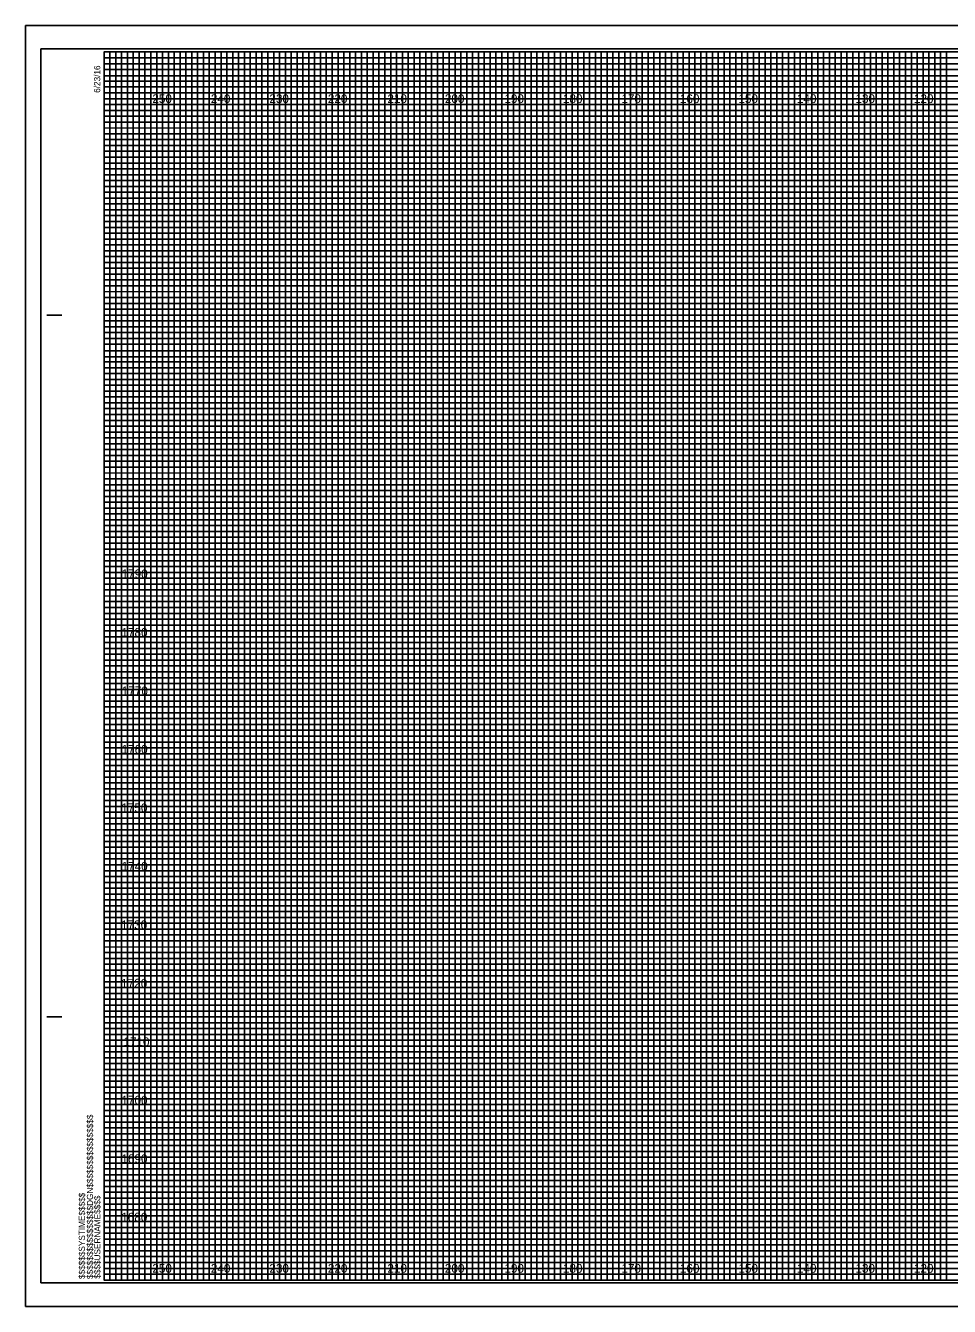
# Model space of a CAD drawing. Extents: x -13 to 1780, y -15 to 3284.
# Drawn here: x 1098.4 to 1256.3, y 208.7 to 427.7 of the extents above; entities that cross this region are included whole.
import ezdxf

# ---------------------------------------------------------------- set-up
doc = ezdxf.new("R2010")
doc.units = 0
for name, color, linetype in [('Prop Retaining Wall', 7, 'Continuous'), ('Prop SS Cut Line', 7, 'Continuous'), ('Prop SS Fill Line', 7, 'Continuous'), ('Prop SS Transition Line', 7, 'Continuous'), ('Prop XS Earthwork Shape', 7, 'Continuous'), ('Prop XS Noise Wall', 7, 'Continuous'), ('Prop XS Station Labels', 7, 'Continuous'), ('Raster_Level_0', 7, 'Continuous'), ('Scratch_Level_3', 7, 'Continuous'), ('Scratch_Level_7', 7, 'Continuous'), ('Typical Bridge Rail CELL', 7, 'Continuous')]:
    doc.layers.add(name, color=color, linetype=linetype)

msp = doc.modelspace()

# ---------------------------------------------------------------- linework, layer by layer
at = {"layer": 'Prop Retaining Wall'}
for p, q in [((1101.99, 378.2), (1104.49, 378.2)), ((1102.09, 378.2), (1104.59, 378.2)), ((1101.99, 258.2), (1104.49, 258.2)), ((1102.09, 258.2), (1104.59, 258.2)), ((1111.79, 213.2), (1111.79, 213.2)), ((1111.79, 213.2), (1111.79, 213.2)), ((1111.79, 213.2), (1111.79, 213.2)), ((1111.79, 213.2), (1111.79, 213.2)), ((1111.79, 213.2), (1111.79, 213.2)), ((1111.79, 213.2), (1111.79, 213.2)), ((1111.79, 213.2), (1111.79, 213.2))]:
    msp.add_line(p, q, dxfattribs=at)
msp.add_lwpolyline([(1431.79, 423.2), (1111.79, 423.2), (1111.79, 213.2), (1431.79, 213.2)], close=True, dxfattribs=at)
at = {"layer": 'Prop SS Cut Line'}
for points in [[(1111.79, 423.2), (1116.79, 423.2), (1116.79, 213.2), (1126.79, 213.2), (1126.79, 423.2), (1136.79, 423.2), (1136.79, 213.2), (1146.79, 213.2), (1146.79, 423.2), (1156.79, 423.2), (1156.79, 213.2), (1166.79, 213.2), (1166.79, 423.2), (1176.79, 423.2), (1176.79, 213.2), (1186.79, 213.2), (1186.79, 423.2), (1196.79, 423.2), (1196.79, 213.2), (1206.79, 213.2), (1206.79, 423.2), (1216.79, 423.2), (1216.79, 213.2), (1226.79, 213.2), (1226.79, 423.2), (1236.79, 423.2), (1236.79, 213.2), (1246.79, 213.2), (1246.79, 423.2), (1256.79, 423.2)], [(1111.79, 418.2), (1386.79, 418.2)], [(1111.79, 398.2), (1431.79, 398.2), (1431.79, 408.2), (1111.79, 408.2)], [(1111.79, 378.2), (1431.79, 378.2), (1431.79, 388.2), (1111.79, 388.2)], [(1111.79, 358.2), (1431.79, 358.2), (1431.79, 368.2), (1111.79, 368.2)], [(1111.79, 338.2), (1431.79, 338.2), (1431.79, 348.2), (1111.79, 348.2)], [(1111.79, 318.2), (1431.79, 318.2), (1431.79, 328.2), (1111.79, 328.2)], [(1111.79, 298.2), (1431.79, 298.2), (1431.79, 308.2), (1111.79, 308.2)], [(1111.79, 278.2), (1431.79, 278.2), (1431.79, 288.2), (1111.79, 288.2)], [(1111.79, 258.2), (1431.79, 258.2), (1431.79, 268.2), (1111.79, 268.2)], [(1111.79, 238.2), (1431.79, 238.2), (1431.79, 248.2), (1111.79, 248.2)], [(1111.79, 218.2), (1431.79, 218.2), (1431.79, 228.2), (1111.79, 228.2)]]:
    msp.add_lwpolyline(points, dxfattribs=at)
at = {"layer": 'Prop SS Fill Line'}
for p, q in [((1121.79, 423.2), (1111.79, 423.2)), ((1121.79, 213.2), (1121.79, 423.2)), ((1141.79, 423.2), (1131.79, 423.2)), ((1131.79, 423.2), (1131.79, 213.2)), ((1141.79, 213.2), (1141.79, 423.2)), ((1161.79, 423.2), (1151.79, 423.2)), ((1151.79, 423.2), (1151.79, 213.2)), ((1161.79, 213.2), (1161.79, 423.2)), ((1181.79, 423.2), (1171.79, 423.2)), ((1171.79, 423.2), (1171.79, 213.2)), ((1181.79, 213.2), (1181.79, 423.2)), ((1201.79, 423.2), (1191.79, 423.2)), ((1191.79, 423.2), (1191.79, 213.2)), ((1201.79, 213.2), (1201.79, 423.2)), ((1221.79, 423.2), (1211.79, 423.2)), ((1211.79, 423.2), (1211.79, 213.2)), ((1221.79, 213.2), (1221.79, 423.2)), ((1241.79, 423.2), (1231.79, 423.2)), ((1231.79, 423.2), (1231.79, 213.2)), ((1241.79, 213.2), (1241.79, 423.2)), ((1261.79, 423.2), (1251.79, 423.2)), ((1251.79, 423.2), (1251.79, 213.2)), ((1131.79, 213.2), (1121.79, 213.2)), ((1151.79, 213.2), (1141.79, 213.2)), ((1171.79, 213.2), (1161.79, 213.2)), ((1191.79, 213.2), (1181.79, 213.2)), ((1211.79, 213.2), (1201.79, 213.2)), ((1231.79, 213.2), (1221.79, 213.2)), ((1251.79, 213.2), (1241.79, 213.2))]:
    msp.add_line(p, q, dxfattribs=at)
for points in [[(1111.79, 413.2), (1431.79, 413.2), (1431.79, 403.2), (1111.79, 403.2)], [(1111.79, 393.2), (1431.79, 393.2), (1431.79, 383.2), (1111.79, 383.2)], [(1111.79, 373.2), (1431.79, 373.2), (1431.79, 363.2), (1111.79, 363.2)], [(1111.79, 353.2), (1431.79, 353.2), (1431.79, 343.2), (1111.79, 343.2)], [(1111.79, 333.2), (1431.79, 333.2), (1431.79, 323.2), (1111.79, 323.2)], [(1111.79, 313.2), (1431.79, 313.2), (1431.79, 303.2), (1111.79, 303.2)], [(1111.79, 293.2), (1431.79, 293.2), (1431.79, 283.2), (1111.79, 283.2)], [(1111.79, 273.2), (1431.79, 273.2), (1431.79, 263.2), (1111.79, 263.2)], [(1111.79, 253.2), (1431.79, 253.2), (1431.79, 243.2), (1111.79, 243.2)], [(1111.79, 233.2), (1431.79, 233.2), (1431.79, 223.2), (1111.79, 223.2)]]:
    msp.add_lwpolyline(points, dxfattribs=at)
at = {"layer": 'Prop SS Transition Line'}
for p, q in [((1111.79, 422.2), (1371.79, 422.2)), ((1371.79, 421.18), (1111.79, 421.18)), ((1111.79, 421.18), (1111.79, 420.2)), ((1111.79, 420.2), (1371.79, 420.2)), ((1371.79, 419.09), (1111.79, 419.09)), ((1111.79, 419.09), (1111.79, 417.2)), ((1111.79, 417.2), (1431.79, 417.2))]:
    msp.add_line(p, q, dxfattribs=at)
for points in [[(1111.79, 416.2), (1381.79, 416.2), (1431.79, 416.2), (1431.79, 415.2), (1111.79, 415.2)], [(1111.79, 414.2), (1431.79, 414.2), (1431.79, 412.2), (1111.79, 412.2)], [(1111.79, 411.2), (1431.79, 411.2), (1431.79, 410.2), (1111.79, 410.18)], [(1111.79, 409.2), (1431.79, 409.2), (1431.79, 407.2), (1111.79, 407.2)], [(1111.79, 406.2), (1431.79, 406.2), (1431.79, 405.2), (1111.79, 405.2)], [(1111.79, 404.2), (1431.79, 404.2), (1431.79, 402.2), (1111.79, 402.2)], [(1111.79, 401.2), (1431.79, 401.2), (1431.79, 400.2), (1111.79, 400.2)], [(1111.79, 399.2), (1431.79, 399.2), (1431.79, 397.2), (1111.79, 397.2)], [(1111.79, 396.2), (1431.79, 396.2), (1431.79, 395.2), (1111.79, 395.2)], [(1111.79, 394.2), (1431.79, 394.2), (1431.79, 392.2), (1111.79, 392.2)], [(1111.79, 391.2), (1431.79, 391.2), (1431.79, 390.2), (1111.79, 390.2)], [(1111.79, 389.2), (1431.79, 389.2), (1431.79, 387.15), (1431.79, 386.2), (1431.79, 385.2), (1111.79, 385.2)], [(1111.79, 387.2), (1431.79, 387.2), (1431.79, 386.2), (1111.79, 386.2)], [(1111.79, 384.2), (1431.79, 384.2), (1431.79, 382.2), (1111.79, 382.23)], [(1111.79, 382.23), (1431.79, 382.2), (1431.79, 381.2), (1111.79, 381.2)], [(1111.79, 380.2), (1431.79, 380.2), (1431.79, 379.2), (1111.79, 379.2)], [(1111.79, 377.2), (1431.79, 377.2), (1431.79, 376.2), (1111.79, 376.2)], [(1111.79, 375.2), (1431.79, 375.2), (1431.79, 374.2), (1111.79, 374.2)], [(1111.72, 372.09), (1431.79, 372.09), (1431.79, 371.08), (1111.72, 371.08)], [(1111.79, 370.2), (1431.79, 370.2), (1431.79, 369.2), (1111.79, 369.2)], [(1111.79, 367.2), (1431.79, 367.2), (1431.79, 366.2), (1111.79, 366.2)], [(1111.79, 365.2), (1431.79, 365.2), (1431.79, 364.2), (1111.79, 364.2)], [(1111.79, 362.2), (1431.79, 362.2), (1431.79, 361.2), (1111.79, 361.2)], [(1111.79, 360.2), (1431.79, 360.2), (1431.79, 359.2), (1111.79, 359.2)], [(1111.79, 357.2), (1431.79, 357.2), (1431.79, 356.2), (1111.79, 356.2)], [(1111.79, 355.2), (1431.79, 355.2), (1431.79, 354.2), (1111.79, 354.2)], [(1111.79, 352.2), (1431.79, 352.2), (1431.78, 351.18), (1111.79, 351.2)], [(1111.79, 350.2), (1431.79, 350.2), (1431.79, 349.2), (1111.79, 349.2)], [(1111.79, 347.2), (1431.79, 347.2), (1431.79, 346.2), (1111.79, 346.2)], [(1111.79, 345.2), (1431.79, 345.2), (1431.79, 344.2), (1111.79, 344.2)], [(1111.79, 342.2), (1431.79, 342.2), (1431.79, 341.2), (1111.79, 341.2)], [(1111.79, 340.2), (1431.79, 340.2), (1431.79, 339.2), (1111.79, 339.2)], [(1111.79, 337.2), (1431.79, 337.2), (1431.79, 336.2), (1111.79, 336.2)], [(1111.79, 335.2), (1431.79, 335.2), (1431.79, 334.2), (1111.79, 334.2)], [(1111.79, 332.2), (1431.79, 332.2), (1431.79, 331.2), (1111.79, 331.2)], [(1111.79, 330.19), (1431.86, 330.11), (1431.79, 329.2), (1111.79, 329.2)], [(1111.79, 327.2), (1431.79, 327.2), (1431.79, 326.2), (1111.79, 326.2)], [(1111.79, 325.2), (1431.79, 325.2), (1431.79, 324.2), (1111.79, 324.2)], [(1111.79, 322.2), (1431.79, 322.2), (1431.79, 321.2), (1111.79, 321.2)], [(1111.79, 320.2), (1431.79, 320.2), (1431.79, 319.2), (1111.79, 319.2)], [(1111.79, 317.2), (1431.79, 317.2), (1431.79, 316.2), (1111.79, 316.2)], [(1111.79, 315.2), (1431.79, 315.2), (1431.79, 314.2), (1111.79, 314.2)], [(1111.79, 312.2), (1431.79, 312.2), (1431.79, 311.2), (1111.79, 311.2)], [(1111.79, 310.2), (1431.79, 310.2), (1431.79, 309.2), (1111.79, 309.2)], [(1111.79, 307.2), (1431.79, 307.2), (1431.79, 306.2), (1111.79, 306.2)], [(1111.79, 305.2), (1431.79, 305.2), (1431.79, 304.2), (1111.79, 304.2)], [(1111.79, 302.2), (1431.79, 302.2), (1431.79, 301.2), (1111.79, 301.2)], [(1111.79, 300.2), (1431.79, 300.2), (1431.79, 299.2), (1111.79, 299.2)], [(1111.79, 297.2), (1431.79, 297.2), (1431.79, 296.2), (1111.79, 296.2)], [(1111.79, 295.2), (1431.79, 295.2), (1431.79, 294.2), (1111.79, 294.2)], [(1111.79, 292.2), (1431.79, 292.2), (1431.78, 291.18), (1111.79, 291.2)], [(1111.79, 290.2), (1431.79, 290.2), (1431.79, 289.2), (1111.79, 289.2)], [(1111.79, 287.2), (1431.79, 287.2), (1431.79, 286.2), (1111.79, 286.2)], [(1111.79, 285.2), (1431.79, 285.2), (1431.79, 284.2), (1111.79, 284.2)], [(1111.79, 282.2), (1431.79, 282.2), (1431.79, 281.2), (1111.79, 281.2)], [(1111.79, 280.2), (1431.79, 280.2), (1431.79, 279.2), (1111.79, 279.2)], [(1111.79, 277.2), (1431.79, 277.2), (1431.79, 276.2), (1111.79, 276.2)], [(1111.79, 275.2), (1431.79, 275.2), (1431.79, 274.2), (1111.79, 274.2)], [(1111.79, 272.2), (1431.79, 272.2), (1431.79, 271.2), (1111.79, 271.2)], [(1111.79, 270.19), (1431.86, 270.11), (1431.79, 269.2), (1111.79, 269.2)], [(1111.79, 267.2), (1431.79, 267.2), (1431.79, 266.2), (1111.79, 266.2)], [(1111.79, 265.2), (1431.79, 265.2), (1431.79, 264.2), (1111.79, 264.2)], [(1111.79, 262.2), (1431.79, 262.2), (1431.79, 261.2), (1111.79, 261.2)], [(1111.79, 260.2), (1431.79, 260.2), (1431.79, 259.2), (1111.79, 259.2)], [(1111.79, 257.2), (1431.79, 257.2), (1431.79, 256.2), (1111.79, 256.2)], [(1111.79, 255.2), (1431.79, 255.2), (1431.79, 254.2), (1111.79, 254.2)], [(1111.79, 252.2), (1431.79, 252.2), (1431.79, 251.2), (1111.79, 251.2)], [(1111.79, 250.2), (1431.79, 250.2), (1431.79, 249.2), (1111.79, 249.2)], [(1111.79, 247.2), (1431.79, 247.2), (1431.79, 246.2), (1111.79, 246.2)], [(1111.79, 245.2), (1431.79, 245.2), (1431.79, 244.2), (1111.79, 244.2)], [(1111.79, 242.2), (1431.79, 242.2), (1431.79, 241.2), (1111.79, 241.2)], [(1111.79, 240.2), (1431.79, 240.2), (1431.79, 239.2), (1111.79, 239.2)], [(1111.79, 237.2), (1431.79, 237.2), (1431.79, 236.2), (1111.79, 236.2)], [(1111.79, 235.2), (1431.79, 235.2), (1431.79, 234.2), (1111.79, 234.2)], [(1111.79, 232.2), (1431.79, 232.2), (1431.79, 231.2), (1111.79, 231.2)], [(1111.79, 230.2), (1431.79, 230.2), (1431.79, 229.2), (1111.79, 229.2)], [(1111.79, 227.2), (1431.79, 227.2), (1431.79, 226.2), (1111.79, 226.2)], [(1111.79, 225.2), (1431.79, 225.2), (1431.79, 224.2), (1111.79, 224.2)], [(1111.79, 222.2), (1431.79, 222.2), (1431.79, 221.2), (1111.79, 221.2)], [(1111.79, 220.2), (1431.79, 220.2), (1431.79, 219.2), (1111.79, 219.2)], [(1111.79, 217.2), (1431.79, 217.2), (1431.79, 216.2), (1111.79, 216.2)], [(1111.79, 215.2), (1431.79, 215.2), (1431.79, 214.2), (1111.79, 214.2)]]:
    msp.add_lwpolyline(points, dxfattribs=at)
at = {"layer": 'Prop XS Earthwork Shape'}
msp.add_lwpolyline([(1098.39, 208.7), (1435.09, 208.7), (1435.09, 427.7), (1098.39, 427.7)], close=True, dxfattribs=at)
at = {"layer": 'Prop XS Noise Wall'}
for p, q in [((1121.79, 213.2), (1121.79, 423.2)), ((1131.79, 213.2), (1131.79, 423.2)), ((1141.79, 213.2), (1141.79, 423.2)), ((1151.79, 213.2), (1151.79, 423.2)), ((1161.79, 213.2), (1161.79, 423.2)), ((1171.79, 213.2), (1171.79, 423.2)), ((1181.79, 213.2), (1181.79, 423.2)), ((1191.79, 213.2), (1191.79, 423.2)), ((1201.79, 213.2), (1201.79, 423.2)), ((1211.79, 213.2), (1211.79, 423.2)), ((1221.79, 213.2), (1221.79, 423.2)), ((1231.79, 213.2), (1231.79, 423.2)), ((1241.79, 213.2), (1241.79, 423.2)), ((1251.79, 213.2), (1251.79, 423.2)), ((1111.79, 413.2), (1431.79, 413.2)), ((1111.79, 403.2), (1431.79, 403.2)), ((1111.79, 393.2), (1431.79, 393.2)), ((1111.79, 383.2), (1431.79, 383.2)), ((1111.79, 373.2), (1431.79, 373.2)), ((1111.79, 363.2), (1431.79, 363.2)), ((1111.79, 353.2), (1431.79, 353.2)), ((1111.79, 343.2), (1431.79, 343.2)), ((1111.79, 333.2), (1431.79, 333.2)), ((1111.79, 323.2), (1431.79, 323.2)), ((1111.79, 313.2), (1431.79, 313.2)), ((1111.79, 303.2), (1431.79, 303.2)), ((1111.79, 293.2), (1431.79, 293.2)), ((1111.79, 283.2), (1431.79, 283.2)), ((1111.79, 273.2), (1431.79, 273.2)), ((1111.79, 263.2), (1431.79, 263.2)), ((1111.79, 253.2), (1431.79, 253.2)), ((1111.79, 243.2), (1431.79, 243.2)), ((1111.79, 233.2), (1431.79, 233.2)), ((1111.79, 223.2), (1431.79, 223.2))]:
    msp.add_line(p, q, dxfattribs=at)
at = {"layer": 'Prop XS Station Labels'}
for p, q in [((1435.09, 427.7), (1098.39, 427.7)), ((1098.39, 427.7), (1098.39, 208.7)), ((1098.39, 208.7), (1435.09, 208.7))]:
    msp.add_line(p, q, dxfattribs=at)
at = {"layer": 'Scratch_Level_7'}
msp.add_lwpolyline([(1100.99, 212.7), (1434.19, 212.7), (1434.19, 423.7), (1100.99, 423.7)], close=True, dxfattribs=at)
at = {"layer": 'Typical Bridge Rail CELL'}
for points in [[(1111.79, 213.2), (1112.79, 213.2), (1112.79, 423.2), (1113.79, 423.2), (1113.79, 213.2)], [(1113.79, 213.2), (1114.79, 213.2), (1114.79, 423.2), (1115.79, 423.2), (1115.79, 213.2)], [(1116.79, 213.2), (1117.79, 213.2), (1117.79, 423.2), (1118.79, 423.2), (1118.79, 213.2)], [(1118.79, 213.2), (1119.79, 213.2), (1119.79, 423.2), (1120.79, 423.2), (1120.79, 213.2)], [(1121.79, 213.2), (1122.79, 213.2), (1122.79, 423.2), (1123.79, 423.2), (1123.79, 213.2)], [(1123.79, 213.2), (1124.79, 213.2), (1124.79, 423.2), (1125.79, 423.2), (1125.79, 213.2)], [(1126.79, 213.2), (1127.79, 213.2), (1127.79, 423.2), (1128.79, 423.2), (1128.79, 213.2)], [(1128.79, 213.2), (1129.79, 213.2), (1129.79, 423.2), (1130.79, 423.2), (1130.79, 213.2)], [(1131.79, 213.2), (1132.79, 213.2), (1132.79, 423.2), (1133.79, 423.2), (1133.79, 213.2)], [(1133.79, 213.2), (1134.79, 213.2), (1134.79, 423.2), (1135.79, 423.2), (1135.79, 213.2)], [(1136.79, 213.2), (1137.79, 213.2), (1137.79, 423.2), (1138.79, 423.2), (1138.79, 213.2)], [(1138.79, 213.2), (1139.79, 213.2), (1139.79, 423.2), (1140.79, 423.2), (1140.79, 213.2)], [(1141.79, 213.2), (1142.79, 213.2), (1142.79, 423.2), (1143.79, 423.2), (1143.79, 213.2)], [(1143.79, 213.2), (1144.79, 213.2), (1144.79, 423.2), (1145.79, 423.2), (1145.79, 213.2)], [(1146.79, 213.2), (1147.79, 213.2), (1147.79, 423.2), (1148.79, 423.2), (1148.79, 213.2)], [(1148.79, 213.2), (1149.79, 213.2), (1149.79, 423.2), (1150.79, 423.2), (1150.79, 213.2)], [(1151.79, 213.2), (1152.79, 213.2), (1152.79, 423.2), (1153.79, 423.2), (1153.79, 213.2)], [(1153.79, 213.2), (1154.79, 213.2), (1154.79, 423.2), (1155.79, 423.2), (1155.79, 213.2)], [(1156.79, 213.2), (1157.79, 213.2), (1157.79, 423.2), (1158.79, 423.2), (1158.79, 213.2)], [(1158.79, 213.2), (1159.79, 213.2), (1159.79, 423.2), (1160.79, 423.2), (1160.79, 213.2)], [(1161.79, 213.2), (1162.79, 213.2), (1162.79, 423.2), (1163.79, 423.2), (1163.79, 213.2)], [(1163.79, 213.2), (1164.79, 213.2), (1164.79, 423.2), (1165.79, 423.2), (1165.79, 213.2)], [(1166.79, 213.2), (1167.79, 213.2), (1167.79, 423.2), (1168.79, 423.2), (1168.79, 213.2)], [(1168.79, 213.2), (1169.79, 213.2), (1169.79, 423.2), (1170.79, 423.2), (1170.79, 213.2)], [(1171.79, 213.2), (1172.79, 213.2), (1172.79, 423.2), (1173.79, 423.2), (1173.79, 213.2)], [(1173.79, 213.2), (1174.79, 213.2), (1174.79, 423.2), (1175.79, 423.2), (1175.79, 213.2)], [(1176.79, 213.2), (1177.79, 213.2), (1177.79, 423.2), (1178.79, 423.2), (1178.79, 213.2)], [(1178.79, 213.2), (1179.79, 213.2), (1179.79, 423.2), (1180.79, 423.2), (1180.79, 213.2)], [(1181.79, 213.2), (1182.79, 213.2), (1182.79, 423.2), (1183.79, 423.2), (1183.79, 213.2)], [(1183.79, 213.2), (1184.79, 213.2), (1184.79, 423.2), (1185.79, 423.2), (1185.79, 213.2)], [(1186.79, 213.2), (1187.79, 213.2), (1187.79, 423.2), (1188.79, 423.2), (1188.79, 213.2)], [(1188.79, 213.2), (1189.79, 213.2), (1189.79, 423.2), (1190.79, 423.2), (1190.79, 213.2)], [(1191.79, 213.2), (1192.79, 213.2), (1192.79, 423.2), (1193.79, 423.2), (1193.79, 213.2)], [(1193.79, 213.2), (1194.79, 213.2), (1194.79, 423.2), (1195.79, 423.2), (1195.79, 213.2)], [(1196.79, 213.2), (1197.79, 213.2), (1197.79, 423.2), (1198.79, 423.2), (1198.79, 213.2)], [(1198.79, 213.2), (1199.79, 213.2), (1199.79, 423.2), (1200.79, 423.2), (1200.79, 213.2)], [(1201.79, 213.2), (1202.79, 213.2), (1202.79, 423.2), (1203.79, 423.2), (1203.79, 213.2)], [(1203.79, 213.2), (1204.79, 213.2), (1204.79, 423.2), (1205.79, 423.2), (1205.79, 213.2)], [(1206.79, 213.2), (1207.79, 213.2), (1207.79, 423.2), (1208.79, 423.2), (1208.79, 213.2)], [(1208.79, 213.2), (1209.79, 213.2), (1209.79, 423.2), (1210.79, 423.2), (1210.79, 213.2)], [(1211.79, 213.2), (1212.79, 213.2), (1212.79, 423.2), (1213.79, 423.2), (1213.79, 213.2)], [(1213.79, 213.2), (1214.79, 213.2), (1214.79, 423.2), (1215.79, 423.2), (1215.79, 213.2)], [(1216.79, 213.2), (1217.79, 213.2), (1217.79, 423.2), (1218.79, 423.2), (1218.79, 213.2)], [(1218.79, 213.2), (1219.79, 213.2), (1219.79, 423.2), (1220.79, 423.2), (1220.79, 213.2)], [(1221.79, 213.2), (1222.79, 213.2), (1222.79, 423.2), (1223.79, 423.2), (1223.79, 213.2)], [(1223.79, 213.2), (1224.79, 213.2), (1224.79, 423.2), (1225.79, 423.2), (1225.79, 213.2)], [(1226.79, 213.2), (1227.79, 213.2), (1227.79, 423.2), (1228.79, 423.2), (1228.79, 213.2)], [(1228.79, 213.2), (1229.79, 213.2), (1229.79, 423.2), (1230.79, 423.2), (1230.79, 213.2)], [(1231.79, 213.2), (1232.79, 213.2), (1232.79, 423.2), (1233.79, 423.2), (1233.79, 213.2)], [(1233.79, 213.2), (1234.79, 213.2), (1234.79, 423.2), (1235.79, 423.2), (1235.79, 213.2)], [(1236.79, 213.2), (1237.79, 213.2), (1237.79, 423.2), (1238.79, 423.2), (1238.79, 213.2)], [(1238.79, 213.2), (1239.79, 213.2), (1239.79, 423.2), (1240.79, 423.2), (1240.79, 213.2)], [(1241.79, 213.2), (1242.79, 213.2), (1242.79, 423.2), (1243.79, 423.2), (1243.79, 213.2)], [(1243.79, 213.2), (1244.79, 213.2), (1244.79, 423.2), (1245.79, 423.2), (1245.79, 213.2)], [(1246.79, 213.2), (1247.79, 213.2), (1247.79, 423.2), (1248.79, 423.2), (1248.79, 213.2)], [(1248.79, 213.2), (1249.79, 213.2), (1249.79, 423.2), (1250.79, 423.2), (1250.79, 213.2)], [(1251.79, 213.2), (1252.79, 213.2), (1252.79, 423.2), (1253.79, 423.2), (1253.79, 213.2)], [(1253.79, 213.2), (1254.79, 213.2), (1254.79, 423.2), (1255.79, 423.2), (1255.79, 213.2)]]:
    msp.add_lwpolyline(points, dxfattribs=at)

# ---------------------------------------------------------------- texts
at = {"layer": 'Prop Retaining Wall'}
for s, p in [('6/23/16', (1111.14, 416.2)), ('$$$$$$$$$$$$$$$$DGN$$$$$$$$$$$$$$$$', (1109.91, 213.38)), ('$$$$$$SYSTIME$$$$$', (1108.53, 213.38)), ('$$$$USERNAME$$$$', (1111.17, 213.43))]:
    msp.add_text(s, height=1.05, rotation=90, dxfattribs=at).set_placement(p)
at = {"layer": 'Raster_Level_0'}
for s, p in [('250', (1120.05, 414.45)), ('240', (1130.05, 414.45)), ('230', (1140.05, 414.45)), ('220', (1150.05, 414.45)), ('210', (1160.23, 414.45)), ('200', (1170.05, 414.45)), ('190', (1180.23, 414.45)), ('180', (1190.23, 414.45)), ('170', (1200.23, 414.45)), ('160', (1210.23, 414.45)), ('150', (1220.23, 414.45)), ('140', (1230.23, 414.45)), ('130', (1240.23, 414.45)), ('120', (1250.23, 414.45)), ('250', (1120.05, 214.45)), ('240', (1130.05, 214.45)), ('230', (1140.05, 214.45)), ('220', (1150.05, 214.45)), ('210', (1160.23, 214.45)), ('200', (1170.05, 214.45)), ('190', (1180.23, 214.45)), ('180', (1190.23, 214.45)), ('170', (1200.23, 214.45)), ('160', (1210.23, 214.45)), ('150', (1220.23, 214.45)), ('140', (1230.23, 214.45)), ('130', (1240.23, 214.45)), ('120', (1250.23, 214.45))]:
    msp.add_text(s, height=1.5, dxfattribs=at).set_placement(p)
at = {"layer": 'Scratch_Level_3'}
for s, p in [('1790', (1114.79, 333.2)), ('1780', (1114.77, 323.2)), ('1770', (1114.83, 313.2)), ('1760', (1114.79, 303.2)), ('1750', (1114.75, 293.2)), ('1740', (1114.79, 283.2)), ('1730', (1114.71, 273.2)), ('1720', (1114.72, 263.2)), ('1710', (1115.1, 253.2)), ('1700', (1114.77, 243.2)), ('1690', (1114.76, 233.2)), ('1680', (1114.73, 223.2))]:
    msp.add_text(s, height=1.5, dxfattribs=at).set_placement(p)

doc.saveas('drawing.dxf')
